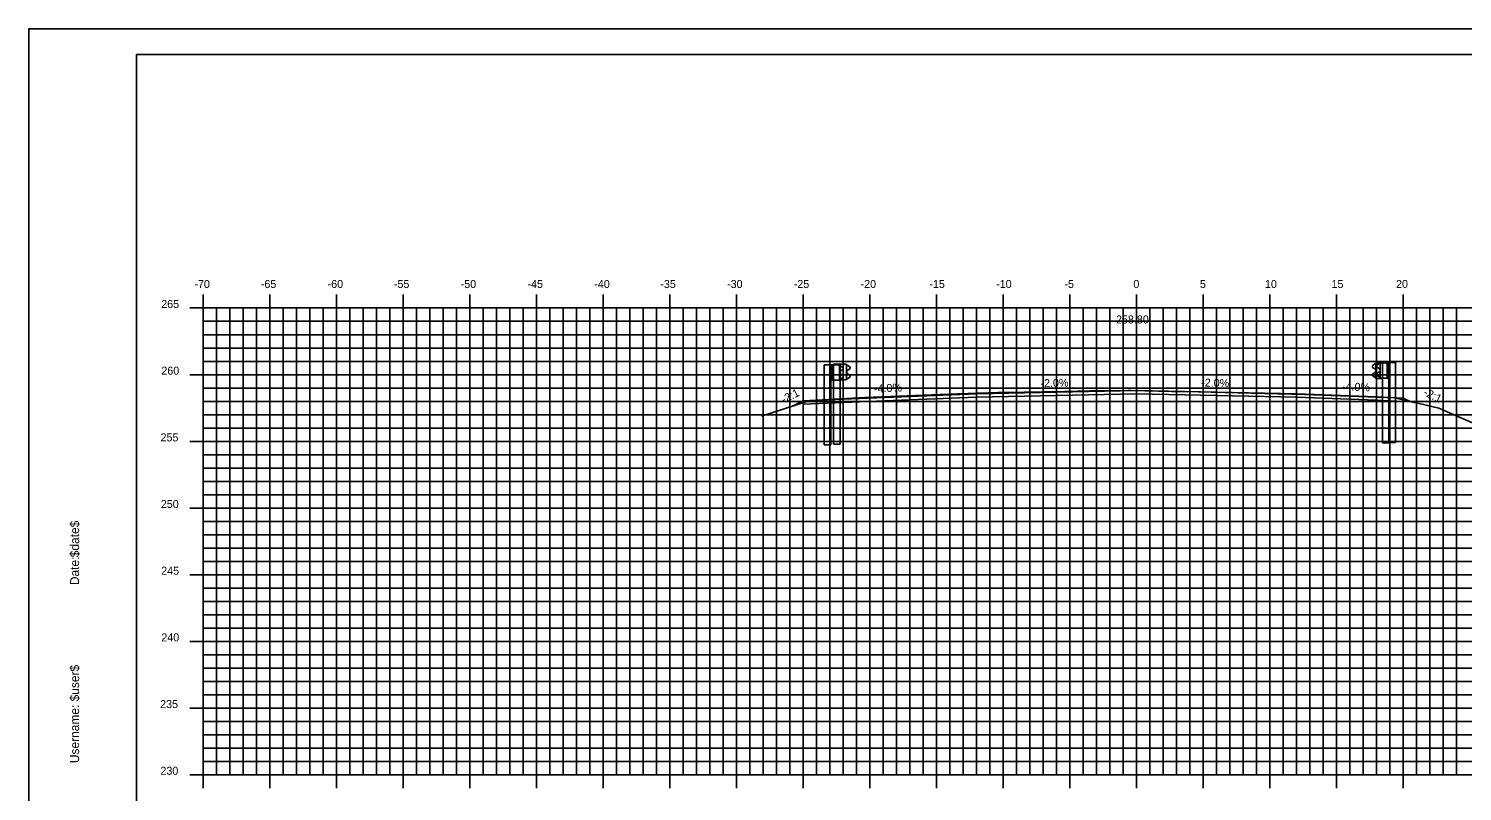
# Model space of a CAD drawing. Extents: x -22 to 1480, y -1511 to 8.
# Drawn here: x 1086.6 to 1194.1, y -131.7 to -74.5 of the extents above; entities that cross this region are included whole.
import ezdxf

# ---------------------------------------------------------------- set-up
doc = ezdxf.new("R2010")
doc.units = 0
for name, color, linetype in [('ANNOTATION', 7, 'Continuous'), ('BORDER', 7, 'Continuous'), ('D_Guardrail_Beam_Lt', 7, 'Continuous'), ('D_Guardrail_Beam_Rt', 7, 'Continuous'), ('D_Roadway_Centerline', 7, 'Continuous'), ('D_Roadway_Centerline_Text', 7, 'Continuous'), ('D_Roadway_Edge_Shoulder', 7, 'Continuous'), ('D_Roadway_Edge_TW', 7, 'Continuous'), ('D_Roadway_SlopeLines', 7, 'Continuous'), ('H_V ANNOTATION', 7, 'Continuous'), ('MAJOR', 7, 'Continuous'), ('MINOR', 7, 'Continuous'), ('PLOT BOUNDARY', 7, 'Continuous'), ('S_Guardrail_Beam', 7, 'Continuous'), ('S_Roadway_Centerline', 7, 'Continuous')]:
    doc.layers.add(name, color=color, linetype=linetype)

msp = doc.modelspace()

# ---------------------------------------------------------------- linework, layer by layer
at = {"layer": 'BORDER'}
for p, q in [((1254.72, -76.47), (1094.72, -76.47)), ((1094.72, -76.47), (1094.72, -181.47))]:
    msp.add_line(p, q, dxfattribs=at)
at = {"layer": 'D_Guardrail_Beam_Lt'}
for p, q in [((1187.9, -99.66), (1187.76, -99.76)), ((1187.76, -99.91), (1187.95, -100.04)), ((1187.99, -99.64), (1187.92, -99.66)), ((1187.99, -99.56), (1188.68, -99.56)), ((1187.99, -100.73), (1187.99, -99.56)), ((1188.51, -99.56), (1188.51, -100.73)), ((1188.62, -99.56), (1188.62, -100.73)), ((1188.68, -99.56), (1189.15, -99.56)), ((1188.68, -99.56), (1188.68, -100.73)), ((1189.15, -99.56), (1189.15, -105.56)), ((1187.95, -100.24), (1187.76, -100.38)), ((1187.76, -100.52), (1187.9, -100.62)), ((1187.92, -100.63), (1187.99, -100.64)), ((1187.99, -100.11), (1187.99, -100.18)), ((1188.68, -100.73), (1187.99, -100.73)), ((1188.66, -105.56), (1188.66, -100.73)), ((1188.66, -105.56), (1189.15, -105.56))]:
    msp.add_line(p, q, dxfattribs=at)
for centre, major_axis, start_param, end_param in [((1187.81, -99.83), (-0.0877, 0), 5.323254, 7.243116), ((1187.93, -99.7), (-0.0417, 0), 4.907132, 5.323254), ((1187.81, -100.45), (-0.0877, 0), 5.323254, 7.243116), ((1187.93, -100.59), (-0.0417, 0), 0.959931, 1.376053), ((1187.91, -100.11), (0.0789, 0), 0, 0.959931), ((1187.91, -100.18), (0.0789, 0), 5.323254, 6.283185)]:
    msp.add_ellipse(centre, major_axis=major_axis, ratio=0.995501, start_param=start_param, end_param=end_param, dxfattribs=at)
at = {"layer": 'D_Guardrail_Beam_Rt'}
for p, q in [((1146.29, -99.72), (1146.29, -105.72)), ((1146.76, -99.72), (1146.29, -99.72)), ((1147.45, -99.72), (1146.76, -99.72)), ((1146.76, -99.72), (1146.76, -100.89)), ((1146.83, -99.72), (1146.83, -100.89)), ((1146.93, -99.72), (1146.93, -100.89)), ((1147.45, -100.89), (1147.45, -99.72)), ((1147.45, -99.8), (1147.53, -99.82)), ((1147.54, -99.82), (1147.68, -99.92)), ((1146.76, -100.89), (1147.45, -100.89)), ((1146.78, -105.72), (1146.78, -100.89)), ((1147.53, -100.79), (1147.45, -100.8)), ((1147.46, -100.27), (1147.46, -100.34)), ((1147.68, -100.07), (1147.49, -100.2)), ((1147.49, -100.4), (1147.68, -100.54)), ((1147.68, -100.68), (1147.54, -100.78)), ((1146.78, -105.72), (1146.29, -105.72))]:
    msp.add_line(p, q, dxfattribs=at)
for centre, major_axis, start_param, end_param in [((1147.52, -99.86), (0.0417, 0), 0.959931, 1.376053), ((1147.63, -99.99), (0.0877, 0), 5.323254, 7.243116), ((1147.53, -100.27), (-0.0789, 0), 5.323254, 6.283185), ((1147.53, -100.34), (-0.0789, 0), 6.283185, 7.243116), ((1147.52, -100.75), (0.0417, 0), 4.907132, 5.323254), ((1147.63, -100.61), (0.0877, 0), 5.323254, 7.243116)]:
    msp.add_ellipse(centre, major_axis=major_axis, ratio=0.995501, start_param=start_param, end_param=end_param, dxfattribs=at)
at = {"layer": 'D_Roadway_Centerline'}
msp.add_lwpolyline([(1143.91, -102.83), (1144.72, -102.42), (1147.72, -102.3), (1157.72, -101.9), (1169.72, -101.66), (1181.72, -101.9), (1187.72, -102.14), (1189.72, -102.22), (1190.23, -102.48)], dxfattribs=at)
at = {"layer": 'D_Roadway_Edge_Shoulder'}
for points in [[(1157.72, -101.9), (1147.72, -102.3), (1147.72, -102.3), (1144.72, -102.42), (1144.72, -102.67), (1147.72, -102.55), (1147.72, -102.55), (1157.72, -102.15)], [(1181.72, -101.9), (1187.72, -102.14), (1187.72, -102.14), (1189.72, -102.22), (1189.72, -102.47), (1187.72, -102.39), (1187.72, -102.39), (1181.72, -102.15)]]:
    msp.add_lwpolyline(points, close=True, dxfattribs=at)
at = {"layer": 'D_Roadway_Edge_TW'}
msp.add_lwpolyline([(1181.72, -102.15), (1181.72, -101.9), (1169.72, -101.66), (1157.72, -101.9), (1157.72, -102.15), (1169.72, -101.91)], close=True, dxfattribs=at)
at = {"layer": 'D_Roadway_SlopeLines'}
for points in [[(1144.72, -102.42), (1143.91, -102.83)], [(1189.72, -102.22), (1190.23, -102.47)]]:
    msp.add_lwpolyline(points, dxfattribs=at)
at = {"layer": 'MAJOR'}
for p, q in [((1099.72, -94.46), (1099.72, -95.47)), ((1104.72, -94.46), (1104.72, -95.47)), ((1109.72, -94.46), (1109.72, -95.47)), ((1114.72, -94.46), (1114.72, -95.47)), ((1119.72, -94.46), (1119.72, -95.47)), ((1124.72, -94.46), (1124.72, -95.47)), ((1129.72, -94.46), (1129.72, -95.47)), ((1134.72, -94.46), (1134.72, -95.47)), ((1139.72, -94.46), (1139.72, -95.47)), ((1144.72, -94.46), (1144.72, -95.47)), ((1149.72, -94.46), (1149.72, -95.47)), ((1154.72, -94.46), (1154.72, -95.47)), ((1159.72, -94.46), (1159.72, -95.47)), ((1164.72, -94.46), (1164.72, -95.47)), ((1169.72, -94.46), (1169.72, -95.47)), ((1174.72, -94.46), (1174.72, -95.47)), ((1179.72, -94.46), (1179.72, -95.47)), ((1184.72, -94.46), (1184.72, -95.47)), ((1189.72, -94.46), (1189.72, -95.47)), ((1098.72, -95.47), (1099.72, -95.47)), ((1099.72, -95.47), (1239.72, -95.47)), ((1099.72, -130.47), (1099.72, -95.47)), ((1099.72, -130.47), (1099.72, -95.47)), ((1099.72, -95.47), (1239.72, -95.47)), ((1104.72, -130.47), (1104.72, -95.47)), ((1109.72, -130.47), (1109.72, -95.47)), ((1114.72, -130.47), (1114.72, -95.47)), ((1119.72, -130.47), (1119.72, -95.47)), ((1124.72, -130.47), (1124.72, -95.47)), ((1129.72, -130.47), (1129.72, -95.47)), ((1134.72, -130.47), (1134.72, -95.47)), ((1139.72, -130.47), (1139.72, -95.47)), ((1144.72, -130.47), (1144.72, -95.47)), ((1149.72, -130.47), (1149.72, -95.47)), ((1154.72, -130.47), (1154.72, -95.47)), ((1159.72, -130.47), (1159.72, -95.47)), ((1164.72, -130.47), (1164.72, -95.47)), ((1169.72, -130.47), (1169.72, -95.47)), ((1174.72, -130.47), (1174.72, -95.47)), ((1179.72, -130.47), (1179.72, -95.47)), ((1184.72, -130.47), (1184.72, -95.47)), ((1189.72, -130.47), (1189.72, -95.47)), ((1098.72, -100.47), (1099.72, -100.47)), ((1099.72, -100.47), (1239.72, -100.47)), ((1098.72, -105.47), (1099.72, -105.47)), ((1099.72, -105.47), (1239.72, -105.47)), ((1098.72, -110.47), (1099.72, -110.47)), ((1099.72, -110.47), (1239.72, -110.47)), ((1098.72, -115.47), (1099.72, -115.47)), ((1099.72, -115.47), (1239.72, -115.47)), ((1098.72, -120.47), (1099.72, -120.47)), ((1099.72, -120.47), (1239.72, -120.47)), ((1098.72, -125.47), (1099.72, -125.47)), ((1099.72, -125.47), (1239.72, -125.47)), ((1098.72, -130.47), (1099.72, -130.47)), ((1099.72, -130.47), (1239.72, -130.47)), ((1099.72, -130.47), (1239.72, -130.47)), ((1099.72, -131.47), (1099.72, -130.47)), ((1104.72, -131.47), (1104.72, -130.47)), ((1109.72, -131.47), (1109.72, -130.47)), ((1114.72, -131.47), (1114.72, -130.47)), ((1119.72, -131.47), (1119.72, -130.47)), ((1124.72, -131.47), (1124.72, -130.47)), ((1129.72, -131.47), (1129.72, -130.47)), ((1134.72, -131.47), (1134.72, -130.47)), ((1139.72, -131.47), (1139.72, -130.47)), ((1144.72, -131.47), (1144.72, -130.47)), ((1149.72, -131.47), (1149.72, -130.47)), ((1154.72, -131.47), (1154.72, -130.47)), ((1159.72, -131.47), (1159.72, -130.47)), ((1164.72, -131.47), (1164.72, -130.47)), ((1169.72, -131.47), (1169.72, -130.47)), ((1174.72, -131.47), (1174.72, -130.47)), ((1179.72, -131.47), (1179.72, -130.47)), ((1184.72, -131.47), (1184.72, -130.47)), ((1189.72, -131.47), (1189.72, -130.47))]:
    msp.add_line(p, q, dxfattribs=at)
at = {"layer": 'MINOR'}
for p, q in [((1100.72, -130.47), (1100.72, -95.47)), ((1101.72, -130.47), (1101.72, -95.47)), ((1102.72, -130.47), (1102.72, -95.47)), ((1103.72, -130.47), (1103.72, -95.47)), ((1105.72, -130.47), (1105.72, -95.47)), ((1106.72, -130.47), (1106.72, -95.47)), ((1107.72, -130.47), (1107.72, -95.47)), ((1108.72, -130.47), (1108.72, -95.47)), ((1110.72, -130.47), (1110.72, -95.47)), ((1111.72, -130.47), (1111.72, -95.47)), ((1112.72, -130.47), (1112.72, -95.47)), ((1113.72, -130.47), (1113.72, -95.47)), ((1115.72, -130.47), (1115.72, -95.47)), ((1116.72, -130.47), (1116.72, -95.47)), ((1117.72, -130.47), (1117.72, -95.47)), ((1118.72, -130.47), (1118.72, -95.47)), ((1120.72, -130.47), (1120.72, -95.47)), ((1121.72, -130.47), (1121.72, -95.47)), ((1122.72, -130.47), (1122.72, -95.47)), ((1123.72, -130.47), (1123.72, -95.47)), ((1125.72, -130.47), (1125.72, -95.47)), ((1126.72, -130.47), (1126.72, -95.47)), ((1127.72, -130.47), (1127.72, -95.47)), ((1128.72, -130.47), (1128.72, -95.47)), ((1130.72, -130.47), (1130.72, -95.47)), ((1131.72, -130.47), (1131.72, -95.47)), ((1132.72, -130.47), (1132.72, -95.47)), ((1133.72, -130.47), (1133.72, -95.47)), ((1135.72, -130.47), (1135.72, -95.47)), ((1136.72, -130.47), (1136.72, -95.47)), ((1137.72, -130.47), (1137.72, -95.47)), ((1138.72, -130.47), (1138.72, -95.47)), ((1140.72, -130.47), (1140.72, -95.47)), ((1141.72, -130.47), (1141.72, -95.47)), ((1142.72, -130.47), (1142.72, -95.47)), ((1143.72, -130.47), (1143.72, -95.47)), ((1145.72, -130.47), (1145.72, -95.47)), ((1146.72, -130.47), (1146.72, -95.47)), ((1147.72, -130.47), (1147.72, -95.47)), ((1148.72, -130.47), (1148.72, -95.47)), ((1150.72, -130.47), (1150.72, -95.47)), ((1151.72, -130.47), (1151.72, -95.47)), ((1152.72, -130.47), (1152.72, -95.47)), ((1153.72, -130.47), (1153.72, -95.47)), ((1155.72, -130.47), (1155.72, -95.47)), ((1156.72, -130.47), (1156.72, -95.47)), ((1157.72, -130.47), (1157.72, -95.47)), ((1158.72, -130.47), (1158.72, -95.47)), ((1160.72, -130.47), (1160.72, -95.47)), ((1161.72, -130.47), (1161.72, -95.47)), ((1162.72, -130.47), (1162.72, -95.47)), ((1163.72, -130.47), (1163.72, -95.47)), ((1165.72, -130.47), (1165.72, -95.47)), ((1166.72, -130.47), (1166.72, -95.47)), ((1167.72, -130.47), (1167.72, -95.47)), ((1168.72, -130.47), (1168.72, -95.47)), ((1170.72, -130.47), (1170.72, -95.47)), ((1171.72, -130.47), (1171.72, -95.47)), ((1172.72, -130.47), (1172.72, -95.47)), ((1173.72, -130.47), (1173.72, -95.47)), ((1175.72, -130.47), (1175.72, -95.47)), ((1176.72, -130.47), (1176.72, -95.47)), ((1177.72, -130.47), (1177.72, -95.47)), ((1178.72, -130.47), (1178.72, -95.47)), ((1180.72, -130.47), (1180.72, -95.47)), ((1181.72, -130.47), (1181.72, -95.47)), ((1182.72, -130.47), (1182.72, -95.47)), ((1183.72, -130.47), (1183.72, -95.47)), ((1185.72, -130.47), (1185.72, -95.47)), ((1186.72, -130.47), (1186.72, -95.47)), ((1187.72, -130.47), (1187.72, -95.47)), ((1188.72, -130.47), (1188.72, -95.47)), ((1190.72, -130.47), (1190.72, -95.47)), ((1191.72, -130.47), (1191.72, -95.47)), ((1192.72, -130.47), (1192.72, -95.47)), ((1193.72, -130.47), (1193.72, -95.47)), ((1099.72, -96.47), (1239.72, -96.47)), ((1099.72, -96.47), (1100.72, -96.47)), ((1099.72, -97.47), (1239.72, -97.47)), ((1099.72, -97.47), (1100.72, -97.47)), ((1099.72, -98.47), (1239.72, -98.47)), ((1099.72, -98.47), (1100.72, -98.47)), ((1099.72, -99.47), (1239.72, -99.47)), ((1099.72, -99.47), (1100.72, -99.47)), ((1099.72, -101.47), (1239.72, -101.47)), ((1099.72, -101.47), (1100.72, -101.47)), ((1099.72, -102.47), (1239.72, -102.47)), ((1099.72, -102.47), (1100.72, -102.47)), ((1099.72, -103.47), (1239.72, -103.47)), ((1099.72, -103.47), (1100.72, -103.47)), ((1099.72, -104.47), (1239.72, -104.47)), ((1099.72, -104.47), (1100.72, -104.47)), ((1099.72, -106.47), (1239.72, -106.47)), ((1099.72, -106.47), (1100.72, -106.47)), ((1099.72, -107.47), (1239.72, -107.47)), ((1099.72, -107.47), (1100.72, -107.47)), ((1099.72, -108.47), (1239.72, -108.47)), ((1099.72, -108.47), (1100.72, -108.47)), ((1099.72, -109.47), (1239.72, -109.47)), ((1099.72, -109.47), (1100.72, -109.47)), ((1099.72, -111.47), (1239.72, -111.47)), ((1099.72, -111.47), (1100.72, -111.47)), ((1099.72, -112.47), (1239.72, -112.47)), ((1099.72, -112.47), (1100.72, -112.47)), ((1099.72, -113.47), (1239.72, -113.47)), ((1099.72, -113.47), (1100.72, -113.47)), ((1099.72, -114.47), (1239.72, -114.47)), ((1099.72, -114.47), (1100.72, -114.47)), ((1099.72, -116.47), (1239.72, -116.47)), ((1099.72, -116.47), (1100.72, -116.47)), ((1099.72, -117.47), (1239.72, -117.47)), ((1099.72, -117.47), (1100.72, -117.47)), ((1099.72, -118.47), (1239.72, -118.47)), ((1099.72, -118.47), (1100.72, -118.47)), ((1099.72, -119.47), (1239.72, -119.47)), ((1099.72, -119.47), (1100.72, -119.47)), ((1099.72, -121.47), (1239.72, -121.47)), ((1099.72, -121.47), (1100.72, -121.47)), ((1099.72, -122.47), (1239.72, -122.47)), ((1099.72, -122.47), (1100.72, -122.47)), ((1099.72, -123.47), (1239.72, -123.47)), ((1099.72, -123.47), (1100.72, -123.47)), ((1099.72, -124.47), (1239.72, -124.47)), ((1099.72, -124.47), (1100.72, -124.47)), ((1099.72, -126.47), (1239.72, -126.47)), ((1099.72, -126.47), (1100.72, -126.47)), ((1099.72, -127.47), (1239.72, -127.47)), ((1099.72, -127.47), (1100.72, -127.47)), ((1099.72, -128.47), (1239.72, -128.47)), ((1099.72, -128.47), (1100.72, -128.47)), ((1099.72, -129.47), (1239.72, -129.47)), ((1099.72, -129.47), (1100.72, -129.47))]:
    msp.add_line(p, q, dxfattribs=at)
at = {"layer": 'PLOT BOUNDARY'}
msp.add_lwpolyline([(1086.63, -184.53), (1256.63, -184.53), (1256.63, -74.53), (1086.63, -74.53)], close=True, dxfattribs=at)
at = {"layer": 'S_Guardrail_Beam'}
for p, q in [((1146.99, -99.69), (1146.99, -105.69)), ((1147.48, -99.69), (1146.99, -99.69)), ((1147.97, -99.69), (1147.48, -99.69)), ((1147.48, -99.69), (1147.48, -100.86)), ((1147.97, -100.86), (1147.97, -99.69)), ((1147.97, -99.76), (1148.05, -99.78)), ((1148.07, -99.79), (1148.21, -99.89)), ((1187.57, -99.68), (1187.43, -99.78)), ((1187.43, -99.92), (1187.62, -100.06)), ((1187.67, -99.66), (1187.59, -99.67)), ((1187.67, -99.59), (1188.16, -99.59)), ((1187.67, -100.75), (1187.67, -99.59)), ((1188.16, -99.59), (1188.65, -99.59)), ((1188.16, -99.59), (1188.16, -100.75)), ((1188.65, -99.59), (1188.65, -105.59)), ((1147.48, -105.69), (1147.48, -100.86)), ((1147.48, -100.86), (1147.97, -100.86)), ((1148.05, -100.77), (1147.97, -100.78)), ((1147.98, -100.23), (1147.98, -100.32)), ((1148.21, -100.03), (1148.02, -100.16)), ((1148.02, -100.38), (1148.21, -100.52)), ((1148.21, -100.66), (1148.07, -100.76)), ((1187.62, -100.28), (1187.43, -100.42)), ((1187.43, -100.56), (1187.57, -100.66)), ((1187.59, -100.67), (1187.67, -100.68)), ((1187.66, -100.12), (1187.66, -100.22)), ((1188.16, -100.75), (1187.67, -100.75)), ((1188.16, -105.59), (1188.16, -100.75)), ((1147.48, -105.69), (1146.99, -105.69)), ((1188.16, -105.59), (1188.65, -105.59))]:
    msp.add_line(p, q, dxfattribs=at)
for centre, major_axis, start_param, end_param in [((1148.04, -99.82), (0.0417, 0), 0.959931, 1.396263), ((1148.16, -99.96), (0.0877, 0), 5.323254, 7.243116), ((1187.48, -99.85), (-0.0877, 0), 5.323254, 7.243116), ((1187.59, -99.71), (-0.0417, 0), 4.886922, 5.323254), ((1148.06, -100.23), (-0.0789, 0), 5.323254, 6.283185), ((1148.06, -100.32), (-0.0789, 0), 6.283185, 7.243116), ((1148.04, -100.73), (0.0417, 0), 4.886922, 5.323254), ((1148.16, -100.59), (0.0877, 0), 5.323254, 7.243116), ((1187.48, -100.49), (-0.0877, 0), 5.323254, 7.243116), ((1187.59, -100.62), (-0.0417, 0), 0.959931, 1.396263), ((1187.58, -100.12), (0.0789, 0), 0, 0.959931), ((1187.58, -100.22), (0.0789, 0), 5.323254, 6.283185)]:
    msp.add_ellipse(centre, major_axis=major_axis, ratio=0.995501, start_param=start_param, end_param=end_param, dxfattribs=at)
at = {"layer": 'S_Roadway_Centerline'}
msp.add_lwpolyline([(1141.59, -103.59), (1144.99, -102.47), (1145.21, -102.4), (1147.08, -102.31), (1149.33, -102.18), (1151.28, -102.1), (1154.34, -101.97), (1156.29, -101.91), (1159.34, -101.8), (1161.3, -101.77), (1164.34, -101.72), (1166.18, -101.69), (1169.06, -101.65), (1169.18, -101.65), (1169.34, -101.65), (1172.36, -101.72), (1174.34, -101.76), (1177.35, -101.83), (1179.34, -101.87), (1182.34, -101.96), (1184.34, -102.02), (1187.06, -102.13), (1189.09, -102.21), (1189.7, -102.35), (1190.42, -102.52), (1190.81, -102.61), (1192.38, -102.99), (1205.56, -108.74)], dxfattribs=at)

# ---------------------------------------------------------------- texts
at = {"layer": 'ANNOTATION'}
for s, rotation, p in [('-2.0%', 1.1458, (1162.52, -101.41)), ('-2.0%', 358.8542, (1174.56, -101.36)), ('-4.0%', 357.7094, (1185.12, -101.64)), ('-2:1', 26.5651, (1143.25, -102.64)), ('-4.0%', 2.2906, (1150.04, -101.81)), ('-2:1', 333.4349, (1191.18, -101.98))]:
    msp.add_text(s, height=0.6, rotation=rotation, dxfattribs=at).set_placement(p)
at = {"layer": 'BORDER'}
for s, p in [('$date$', (1090.41, -114.16)), ('Date:', (1090.41, -116.25)), ('$user$', (1090.41, -124.97)), ('Username:', (1090.41, -129.6))]:
    msp.add_text(s, height=0.67, rotation=90, dxfattribs=at).set_placement(p)
at = {"layer": 'D_Roadway_Centerline'}
for s, p in [('C', (1169.72, -101.66)), ('L', (1169.72, -101.67))]:
    msp.add_text(s, height=0.0146, dxfattribs=at).set_placement(p)
at = {"layer": 'D_Roadway_Centerline_Text'}
msp.add_text('258.80', height=0.6, dxfattribs=at).set_placement((1168.18, -96.63))
at = {"layer": 'H_V ANNOTATION'}
for s, p in [('-70', (1099.06, -93.97)), ('-65', (1104.04, -93.97)), ('-60', (1109.05, -93.97)), ('-55', (1114.02, -93.97)), ('-50', (1119.03, -93.97)), ('-45', (1124.04, -93.97)), ('-40', (1129.05, -93.97)), ('-35', (1134, -93.97)), ('-30', (1139.01, -93.97)), ('-25', (1144.01, -93.97)), ('-20', (1149.02, -93.97)), ('-15', (1154.18, -93.97)), ('-10', (1159.19, -93.97)), ('-5', (1164.31, -93.97)), ('0', (1169.48, -93.97)), ('5', (1174.47, -93.97)), ('10', (1179.35, -93.97)), ('15', (1184.34, -93.97)), ('20', (1189.18, -93.97)), ('265', (1096.57, -95.47)), ('260', (1096.58, -100.47)), ('255', (1096.52, -105.47)), ('250', (1096.54, -110.47)), ('245', (1096.57, -115.47)), ('240', (1096.58, -120.47)), ('235', (1096.49, -125.47)), ('230', (1096.51, -130.47))]:
    msp.add_text(s, height=0.6, dxfattribs=at).set_placement(p)

doc.saveas('drawing.dxf')
